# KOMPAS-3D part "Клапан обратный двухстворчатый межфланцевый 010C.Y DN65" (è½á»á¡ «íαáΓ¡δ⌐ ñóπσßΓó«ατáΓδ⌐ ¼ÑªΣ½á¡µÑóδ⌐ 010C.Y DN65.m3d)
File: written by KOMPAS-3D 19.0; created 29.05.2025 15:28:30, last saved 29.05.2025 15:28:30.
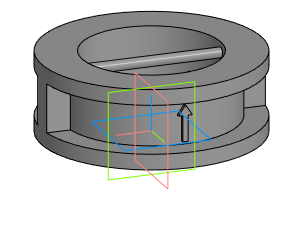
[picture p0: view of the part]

Document properties: Полное имя файла: E:\Dendor Работа Сачек\3D для проекитирвщиков\5.2 Тип 010C, 010C.Y Клапан обратный двухстворчатый межфланцевый\stp_Клапан обратный двухстворчатый межфланцевый 010C.Y\Клапан обратный двухстворчатый межфланцевый 010C.Y DN65.m3d

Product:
- Part/product: Клапан обратный двухстворчатый межфланцевый 010C.Y DN65

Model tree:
1. Операция без истории:1  (labels: Клапан обратный двухстворчатый межфланцевый 010C.Y DN65)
